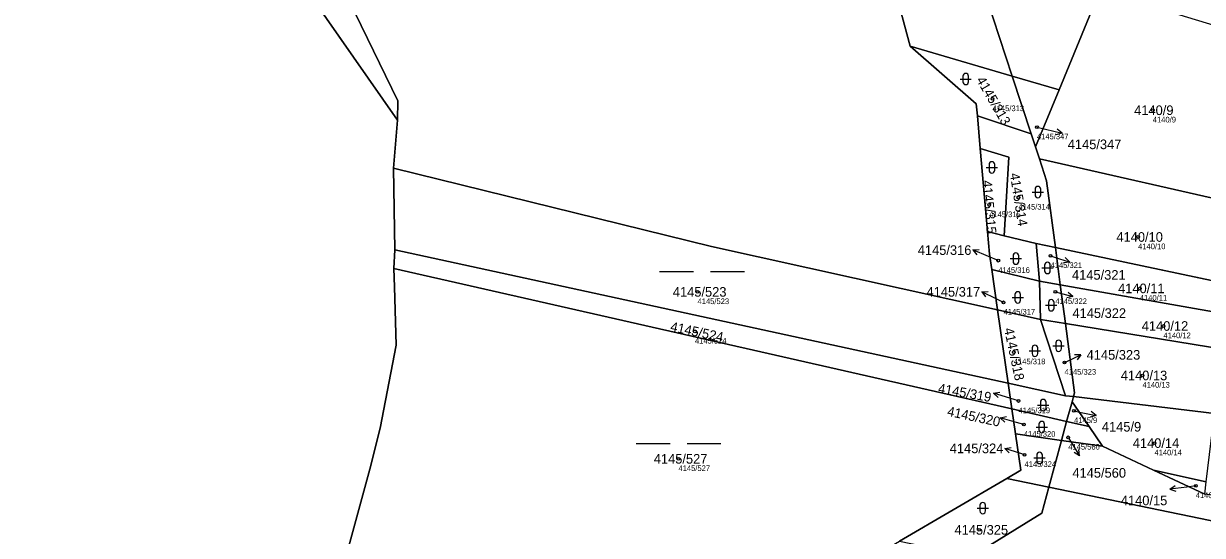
# Model space of a CAD drawing. Extents: x -739214 to -733252, y -1147612 to -1142842.
# Drawn here: x -736257.4 to -736049, y -1146646.4 to -1146556 of the extents above; entities that cross this region are included whole.
import ezdxf

# ---------------------------------------------------------------- set-up
doc = ezdxf.new("R2010")
doc.units = 0
for name, color, linetype in [('Definiční body', 7, 'Continuous'), ('Hranice parcel', 7, 'Continuous'), ('Parcelní čísla', 7, 'Continuous'), ('Polygon parcely', 7, 'Continuous'), ('Pop  PČ popisy', 7, 'Continuous'), ('Značky kultur', 7, 'Continuous')]:
    doc.layers.add(name, color=color, linetype=linetype)

msp = doc.modelspace()

# ---------------------------------------------------------------- linework, layer by layer
at = {"layer": 'Definiční body'}
for centre in [(-736086.12, -1146569.27), (-736057.78, -1146571.27), (-736078.26, -1146574.25), (-736086.7, -1146588.01), (-736081.54, -1146586.68), (-736060.38, -1146593.67), (-736085.09, -1146597.86), (-736075.86, -1146597), (-736138.25, -1146603.38), (-736075.01, -1146603.37), (-736060.08, -1146602.76), (-736084.16, -1146605.23), (-736138.71, -1146610.36), (-736055.9, -1146609.41), (-736082.35, -1146614.01), (-736073.38, -1146615.86), (-736059.61, -1146618.15), (-736081.52, -1146622.66), (-736071.7, -1146624.41), (-736080.57, -1146626.83), (-736072.73, -1146629.1), (-736057.49, -1146630.11), (-736141.62, -1146632.89), (-736080.46, -1146632.17), (-736050.19, -1146637.67), (-736088.47, -1146645.44)]:
    msp.add_circle(centre, 0.25, dxfattribs=at)
at = {"layer": 'Hranice parcel'}
for p, q in [((-736216.79, -1146536.45), (-736191.26, -1146573.01)), ((-736100.68, -1146559.92), (-736082.62, -1146565.24)), ((-736100.68, -1146559.92), (-736088.98, -1146570.14)), ((-736082.62, -1146565.24), (-736074.36, -1146567.67)), ((-736079.28, -1146575.43), (-736082.62, -1146565.24)), ((-736074.36, -1146567.67), (-736078.52, -1146577.76)), ((-736088.98, -1146570.14), (-736088.79, -1146572.26)), ((-736191.26, -1146573.01), (-736191.97, -1146581.49)), ((-736088.79, -1146572.26), (-736079.28, -1146575.43)), ((-736088.79, -1146572.26), (-736088.28, -1146578.06)), ((-736078.52, -1146577.76), (-736079.28, -1146575.43)), ((-736088.28, -1146578.06), (-736087, -1146592.71)), ((-736078.52, -1146577.76), (-736077.83, -1146579.87)), ((-736191.97, -1146581.49), (-736191.78, -1146595.93)), ((-736077.83, -1146579.87), (-736041, -1146588.22)), ((-736087, -1146592.71), (-736084.04, -1146593.47)), ((-736084.04, -1146593.47), (-736078.4, -1146594.8)), ((-736191.78, -1146595.93), (-736191.94, -1146599.24)), ((-736191.78, -1146595.93), (-736083.34, -1146619.53)), ((-736078.4, -1146594.8), (-736075.01, -1146595.52)), ((-736077.83, -1146601.47), (-736078.4, -1146594.8)), ((-736075.01, -1146595.52), (-736043.25, -1146602.28)), ((-736075.01, -1146595.52), (-736074.14, -1146602.12)), ((-736191.94, -1146599.24), (-736082.68, -1146624.08)), ((-736086.25, -1146599.44), (-736077.83, -1146601.47)), ((-736086.25, -1146599.44), (-736085.22, -1146606.58)), ((-736077.61, -1146608.26), (-736077.83, -1146601.47)), ((-736077.83, -1146601.47), (-736074.14, -1146602.12)), ((-736074.14, -1146602.12), (-736044.08, -1146607.44)), ((-736074.14, -1146602.12), (-736073.24, -1146608.97)), ((-736085.22, -1146606.58), (-736077.61, -1146608.26)), ((-736085.22, -1146606.58), (-736083.34, -1146619.53)), ((-736073.24, -1146621.73), (-736077.61, -1146608.26)), ((-736077.61, -1146608.26), (-736073.24, -1146608.97)), ((-736073.24, -1146608.97), (-736045.06, -1146613.54)), ((-736083.34, -1146619.53), (-736073.24, -1146621.73)), ((-736083.34, -1146619.53), (-736082.68, -1146624.08)), ((-736071.82, -1146621.9), (-736073.24, -1146621.73)), ((-736072.06, -1146622.79), (-736073.01, -1146626.28)), ((-736071.82, -1146621.9), (-736072.06, -1146622.79)), ((-736069.06, -1146627.18), (-736072.06, -1146622.79)), ((-736071.82, -1146621.9), (-736046.87, -1146624.86)), ((-736082.68, -1146624.08), (-736073.01, -1146626.28)), ((-736082.68, -1146624.08), (-736082.04, -1146628.49)), ((-736073.92, -1146629.63), (-736073.01, -1146626.28)), ((-736073.01, -1146626.28), (-736069.06, -1146627.18)), ((-736069.06, -1146627.18), (-736066.69, -1146630.64)), ((-736082.04, -1146628.49), (-736073.92, -1146629.63)), ((-736076.17, -1146637.88), (-736073.92, -1146629.63)), ((-736073.92, -1146629.63), (-736066.69, -1146630.64)), ((-736066.69, -1146630.64), (-736057.67, -1146634.87)), ((-736057.67, -1146634.87), (-736048.33, -1146636.94)), ((-736057.67, -1146634.87), (-736048.59, -1146639.13)), ((-736083.6, -1146636.35), (-736102.54, -1146647.43)), ((-736083.6, -1146636.35), (-736076.17, -1146637.88)), ((-736076.17, -1146637.88), (-736001.45, -1146653.31))]:
    msp.add_line(p, q, dxfattribs=at)
for points in [[(-736191.26, -1146573.01), (-736191.2, -1146569.6), (-736240.72, -1146467.85)], [(-736142.92, -1146500.2), (-736123.16, -1146523.78), (-736105.39, -1146542.41), (-736100.68, -1146559.92)], [(-736082.62, -1146565.24), (-736094.95, -1146527.58), (-736116.32, -1146499.99)], [(-736067.53, -1146550.01), (-736067.66, -1146551.39), (-736074.36, -1146567.67)], [(-736088.28, -1146578.06), (-736083.25, -1146579.57), (-736084.04, -1146593.47)], [(-736191.97, -1146581.49), (-736135.8, -1146595.37), (-736085.22, -1146606.58)], [(-736077.83, -1146579.87), (-736076.55, -1146583.77), (-736075.01, -1146595.52)], [(-736087, -1146592.71), (-736086.65, -1146596.69), (-736086.25, -1146599.44)], [(-736191.94, -1146599.24), (-736191.82, -1146602.51), (-736191.51, -1146612.78), (-736194.36, -1146627.44), (-736196.17, -1146634.72), (-736200.09, -1146648.96)], [(-736073.24, -1146608.97), (-736071.64, -1146621.23), (-736071.82, -1146621.9)], [(-736082.04, -1146628.49), (-736081.11, -1146634.89), (-736083.6, -1146636.35)], [(-736089.74, -1146650.09), (-736077.42, -1146642.47), (-736076.17, -1146637.88)]]:
    msp.add_lwpolyline(points, dxfattribs=at)
at = {"layer": 'Polygon parcely'}
for points in [[(-736191.2, -1146569.6), (-736240.72, -1146467.85), (-736248.59, -1146469.28), (-736216.79, -1146536.45), (-736191.26, -1146573.01)], [(-736094.95, -1146527.58), (-736116.32, -1146499.99), (-736146.34, -1146489.4), (-736142.92, -1146500.2), (-736123.16, -1146523.78), (-736105.39, -1146542.41), (-736100.68, -1146559.92), (-736082.62, -1146565.24)], [(-736074.36, -1146567.67), (-736067.66, -1146551.39), (-736067.53, -1146550.01), (-736066.51, -1146539.58), (-736066.95, -1146526.54), (-736067.27, -1146517.23), (-736116.32, -1146499.99), (-736094.95, -1146527.58), (-736082.62, -1146565.24)], [(-736074.36, -1146567.67), (-736078.52, -1146577.76), (-736077.83, -1146579.87), (-736041, -1146588.22), (-736038.99, -1146575.71), (-736035.66, -1146559.73), (-736067.53, -1146550.01), (-736067.66, -1146551.39)], [(-736088.98, -1146570.14), (-736088.79, -1146572.26), (-736079.28, -1146575.43), (-736082.62, -1146565.24), (-736100.68, -1146559.92)], [(-736078.52, -1146577.76), (-736074.36, -1146567.67), (-736082.62, -1146565.24), (-736079.28, -1146575.43)], [(-736088.28, -1146578.06), (-736083.25, -1146579.57), (-736084.04, -1146593.47), (-736078.4, -1146594.8), (-736075.01, -1146595.52), (-736076.55, -1146583.77), (-736077.83, -1146579.87), (-736078.52, -1146577.76), (-736079.28, -1146575.43), (-736088.79, -1146572.26)], [(-736087, -1146592.71), (-736084.04, -1146593.47), (-736083.25, -1146579.57), (-736088.28, -1146578.06)], [(-736083.34, -1146619.53), (-736085.22, -1146606.58), (-736135.8, -1146595.37), (-736191.97, -1146581.49), (-736191.78, -1146595.93)], [(-736043.25, -1146602.28), (-736041, -1146588.22), (-736077.83, -1146579.87), (-736076.55, -1146583.77), (-736075.01, -1146595.52)], [(-736086.65, -1146596.69), (-736086.25, -1146599.44), (-736077.83, -1146601.47), (-736078.4, -1146594.8), (-736084.04, -1146593.47), (-736087, -1146592.71)], [(-736082.68, -1146624.08), (-736083.34, -1146619.53), (-736191.78, -1146595.93), (-736191.94, -1146599.24)], [(-736074.14, -1146602.12), (-736075.01, -1146595.52), (-736078.4, -1146594.8), (-736077.83, -1146601.47)], [(-736044.08, -1146607.44), (-736043.25, -1146602.28), (-736075.01, -1146595.52), (-736074.14, -1146602.12)], [(-736191.51, -1146612.78), (-736194.36, -1146627.44), (-736196.17, -1146634.72), (-736200.09, -1146648.96), (-736167.56, -1146656.18), (-736132.29, -1146663.24), (-736131.9, -1146662.5), (-736122.58, -1146659.16), (-736112.56, -1146653.29), (-736102.54, -1146647.43), (-736083.6, -1146636.35), (-736081.11, -1146634.89), (-736082.04, -1146628.49), (-736082.68, -1146624.08), (-736191.94, -1146599.24), (-736191.82, -1146602.51)], [(-736085.22, -1146606.58), (-736077.61, -1146608.26), (-736077.83, -1146601.47), (-736086.25, -1146599.44)], [(-736073.24, -1146608.97), (-736074.14, -1146602.12), (-736077.83, -1146601.47), (-736077.61, -1146608.26)], [(-736074.14, -1146602.12), (-736073.24, -1146608.97), (-736045.06, -1146613.54), (-736044.08, -1146607.44)], [(-736073.24, -1146621.73), (-736077.61, -1146608.26), (-736085.22, -1146606.58), (-736083.34, -1146619.53)], [(-736071.82, -1146621.9), (-736071.64, -1146621.23), (-736073.24, -1146608.97), (-736077.61, -1146608.26), (-736073.24, -1146621.73)], [(-736073.24, -1146608.97), (-736071.64, -1146621.23), (-736071.82, -1146621.9), (-736046.87, -1146624.86), (-736045.06, -1146613.54)], [(-736073.01, -1146626.28), (-736072.06, -1146622.79), (-736071.82, -1146621.9), (-736073.24, -1146621.73), (-736083.34, -1146619.53), (-736082.68, -1146624.08)], [(-736072.06, -1146622.79), (-736073.01, -1146626.28), (-736069.06, -1146627.18)], [(-736048.33, -1146636.94), (-736046.87, -1146624.86), (-736071.82, -1146621.9), (-736072.06, -1146622.79), (-736069.06, -1146627.18), (-736066.69, -1146630.64), (-736057.67, -1146634.87)], [(-736082.04, -1146628.49), (-736073.92, -1146629.63), (-736073.01, -1146626.28), (-736082.68, -1146624.08)], [(-736073.92, -1146629.63), (-736066.69, -1146630.64), (-736069.06, -1146627.18), (-736073.01, -1146626.28)], [(-736081.11, -1146634.89), (-736083.6, -1146636.35), (-736076.17, -1146637.88), (-736073.92, -1146629.63), (-736082.04, -1146628.49)], [(-736001.45, -1146653.31), (-736024.71, -1146642.17), (-736048.59, -1146639.13), (-736057.67, -1146634.87), (-736066.69, -1146630.64), (-736073.92, -1146629.63), (-736076.17, -1146637.88)], [(-736048.59, -1146639.13), (-736048.33, -1146636.94), (-736057.67, -1146634.87)], [(-736089.74, -1146650.09), (-736077.42, -1146642.47), (-736076.17, -1146637.88), (-736083.6, -1146636.35), (-736102.54, -1146647.43)], [(-735980.05, -1146665.11), (-736001.45, -1146653.31), (-736076.17, -1146637.88), (-736077.42, -1146642.47), (-736089.74, -1146650.09), (-736037.76, -1146661.36), (-735972.21, -1146674.51)]]:
    msp.add_lwpolyline(points, close=True, dxfattribs=at)
for points in [[(-736240.72, -1146467.85), (-736191.2, -1146569.6), (-736191.26, -1146573.01), (-736191.97, -1146581.49), (-736135.8, -1146595.37), (-736085.22, -1146606.58), (-736086.25, -1146599.44), (-736086.65, -1146596.69), (-736087, -1146592.71), (-736088.28, -1146578.06), (-736088.79, -1146572.26), (-736088.98, -1146570.14), (-736100.68, -1146559.92), (-736105.39, -1146542.41)], [(-736446.12, -1146664.77), (-736250, -1146692.16), (-736227.9, -1146695.24), (-736223.78, -1146688.92), (-736215.38, -1146679.7), (-736206.12, -1146668.34), (-736205.38, -1146667.25), (-736200.09, -1146648.96), (-736196.17, -1146634.72), (-736194.36, -1146627.44), (-736191.51, -1146612.78), (-736191.82, -1146602.51), (-736191.94, -1146599.24), (-736191.78, -1146595.93), (-736191.97, -1146581.49), (-736191.26, -1146573.01), (-736216.79, -1146536.45)]]:
    msp.add_lwpolyline(points, dxfattribs=at)
at = {"layer": 'Pop  PČ popisy'}
for p, q in [((-736078.26, -1146574.25), (-736076.74, -1146574.62)), ((-736076.74, -1146574.62), (-736073.83, -1146575.35)), ((-736073.83, -1146575.35), (-736074.92, -1146575.59)), ((-736073.83, -1146575.35), (-736074.68, -1146574.62)), ((-736089.58, -1146595.97), (-736088.46, -1146595.9)), ((-736086.82, -1146597.14), (-736089.58, -1146595.97)), ((-736089.58, -1146595.97), (-736088.86, -1146596.82)), ((-736085.09, -1146597.86), (-736086.82, -1146597.14)), ((-736075.86, -1146597), (-736075.31, -1146597.18)), ((-736075.31, -1146597.18), (-736072.46, -1146598.11)), ((-736072.46, -1146598.11), (-736073.56, -1146598.27)), ((-736072.46, -1146598.11), (-736073.25, -1146597.32)), ((-736088.03, -1146603.35), (-736086.91, -1146603.34)), ((-736085.33, -1146604.67), (-736088.03, -1146603.35)), ((-736088.03, -1146603.35), (-736087.35, -1146604.24)), ((-736075.01, -1146603.37), (-736074.79, -1146603.43)), ((-736074.79, -1146603.43), (-736071.89, -1146604.21)), ((-736071.89, -1146604.21), (-736072.99, -1146604.43)), ((-736071.89, -1146604.21), (-736072.73, -1146603.46)), ((-736084.16, -1146605.23), (-736085.33, -1146604.67)), ((-736073.2, -1146615.78), (-736070.48, -1146614.51)), ((-736070.48, -1146614.51), (-736071.6, -1146614.48)), ((-736070.48, -1146614.51), (-736071.18, -1146615.39)), ((-736073.38, -1146615.86), (-736073.2, -1146615.78)), ((-736085.93, -1146621.3), (-736084.83, -1146621.12)), ((-736083.06, -1146622.18), (-736085.93, -1146621.3)), ((-736085.93, -1146621.3), (-736085.12, -1146622.07)), ((-736081.52, -1146622.66), (-736083.06, -1146622.18)), ((-736071.7, -1146624.41), (-736070.72, -1146624.62)), ((-736070.72, -1146624.62), (-736067.79, -1146625.24)), ((-736067.79, -1146625.24), (-736068.87, -1146625.53)), ((-736067.79, -1146625.24), (-736068.66, -1146624.55)), ((-736084.78, -1146625.63), (-736083.67, -1146625.43)), ((-736081.89, -1146626.46), (-736084.78, -1146625.63)), ((-736084.78, -1146625.63), (-736083.95, -1146626.39)), ((-736080.57, -1146626.83), (-736081.89, -1146626.46)), ((-736072.73, -1146629.1), (-736072.31, -1146629.79)), ((-736083.94, -1146631.04), (-736082.84, -1146630.88)), ((-736081.09, -1146631.97), (-736083.94, -1146631.04)), ((-736083.94, -1146631.04), (-736083.15, -1146631.83)), ((-736072.31, -1146629.79), (-736070.76, -1146632.36)), ((-736070.76, -1146632.36), (-736070.85, -1146631.25)), ((-736080.46, -1146632.17), (-736081.09, -1146631.97)), ((-736070.76, -1146632.36), (-736071.71, -1146631.76)), ((-736054.76, -1146638.25), (-736053.83, -1146637.63)), ((-736051.78, -1146637.88), (-736054.76, -1146638.25)), ((-736050.19, -1146637.67), (-736051.78, -1146637.88)), ((-736054.76, -1146638.25), (-736053.7, -1146638.62))]:
    msp.add_line(p, q, dxfattribs=at)
at = {"layer": 'Značky kultur'}
for p, q in [((-736091.86, -1146565.75), (-736089.86, -1146565.75)), ((-736091.36, -1146565.25), (-736091.36, -1146566.25)), ((-736090.36, -1146566.25), (-736090.36, -1146565.25)), ((-736087.22, -1146581.37), (-736085.22, -1146581.37)), ((-736086.72, -1146580.87), (-736086.72, -1146581.87)), ((-736085.72, -1146581.87), (-736085.72, -1146580.87)), ((-736079.09, -1146585.73), (-736077.09, -1146585.73)), ((-736078.59, -1146585.23), (-736078.59, -1146586.23)), ((-736077.59, -1146586.23), (-736077.59, -1146585.23)), ((-736082.99, -1146597.5), (-736080.99, -1146597.5)), ((-736082.49, -1146597), (-736082.49, -1146598)), ((-736081.49, -1146598), (-736081.49, -1146597)), ((-736144.98, -1146599.75), (-736138.98, -1146599.75)), ((-736135.98, -1146599.75), (-736129.98, -1146599.75)), ((-736077.4, -1146599.15), (-736075.4, -1146599.15)), ((-736076.9, -1146598.65), (-736076.9, -1146599.65)), ((-736075.9, -1146599.65), (-736075.9, -1146598.65)), ((-736082.66, -1146604.35), (-736080.66, -1146604.35)), ((-736082.16, -1146603.85), (-736082.16, -1146604.85)), ((-736081.16, -1146604.85), (-736081.16, -1146603.85)), ((-736076.73, -1146605.75), (-736074.73, -1146605.75)), ((-736076.23, -1146605.25), (-736076.23, -1146606.25)), ((-736075.23, -1146606.25), (-736075.23, -1146605.25)), ((-736074.93, -1146612.41), (-736074.93, -1146613.41)), ((-736073.93, -1146613.41), (-736073.93, -1146612.41)), ((-736079.61, -1146613.79), (-736077.61, -1146613.79)), ((-736079.11, -1146613.29), (-736079.11, -1146614.29)), ((-736078.11, -1146614.29), (-736078.11, -1146613.29)), ((-736075.43, -1146612.91), (-736073.43, -1146612.91)), ((-736077.66, -1146622.89), (-736077.66, -1146623.89)), ((-736076.66, -1146623.89), (-736076.66, -1146622.89)), ((-736078.16, -1146623.39), (-736076.16, -1146623.39)), ((-736078.42, -1146627.27), (-736076.42, -1146627.27)), ((-736077.92, -1146626.77), (-736077.92, -1146627.77)), ((-736076.92, -1146627.77), (-736076.92, -1146626.77)), ((-736149.11, -1146630.19), (-736143.11, -1146630.19)), ((-736140.11, -1146630.19), (-736134.11, -1146630.19)), ((-736078.81, -1146632.74), (-736076.81, -1146632.74)), ((-736078.31, -1146632.24), (-736078.31, -1146633.24)), ((-736077.31, -1146633.24), (-736077.31, -1146632.24)), ((-736088.85, -1146641.6), (-736086.85, -1146641.6)), ((-736088.35, -1146641.1), (-736088.35, -1146642.1)), ((-736087.35, -1146642.1), (-736087.35, -1146641.1))]:
    msp.add_line(p, q, dxfattribs=at)
for centre, start, end in [((-736090.86, -1146565.25), 0, 180), ((-736090.86, -1146566.25), 180, 359.9879), ((-736086.22, -1146580.87), 0, 180), ((-736086.22, -1146581.87), 180, 359.9879), ((-736078.09, -1146585.23), 0, 180), ((-736078.09, -1146586.23), 180, 359.9879), ((-736081.99, -1146597), 0, 180), ((-736081.99, -1146598), 180, 359.9879), ((-736076.4, -1146598.65), 0, 180), ((-736076.4, -1146599.65), 180, 359.9879), ((-736081.66, -1146603.85), 0, 180), ((-736081.66, -1146604.85), 180, 359.9879), ((-736075.73, -1146605.25), 0, 180), ((-736075.73, -1146606.25), 180, 359.9879), ((-736078.61, -1146613.29), 0, 180), ((-736074.43, -1146612.41), 0, 180), ((-736078.61, -1146614.29), 180, 359.9879), ((-736074.43, -1146613.41), 180, 359.9879), ((-736077.16, -1146622.89), 0, 180), ((-736077.16, -1146623.89), 180, 359.9879), ((-736077.42, -1146626.77), 0, 180), ((-736077.42, -1146627.77), 180, 359.9879), ((-736077.81, -1146632.24), 0, 180), ((-736077.81, -1146633.24), 180, 359.9879), ((-736087.85, -1146641.1), 0, 180), ((-736087.85, -1146642.1), 180, 359.9879)]:
    msp.add_arc(centre, 0.5, start, end, dxfattribs=at)

# ---------------------------------------------------------------- texts
at = {"layer": 'Definiční body'}
for s, p in [('4145/313', (-736086.12, -1146571.43)), ('4140/9', (-736057.78, -1146573.43)), ('4145/347', (-736078.26, -1146576.41)), ('4145/314', (-736081.54, -1146588.84)), ('4145/315', (-736086.7, -1146590.17)), ('4140/10', (-736060.38, -1146595.83)), ('4145/321', (-736075.86, -1146599.16)), ('4145/316', (-736085.09, -1146600.02)), ('4145/523', (-736138.25, -1146605.54)), ('4145/322', (-736075.01, -1146605.53)), ('4140/11', (-736060.08, -1146604.92)), ('4145/317', (-736084.16, -1146607.39)), ('4140/12', (-736055.9, -1146611.57)), ('4145/524', (-736138.71, -1146612.52)), ('4145/318', (-736082.35, -1146616.17)), ('4145/323', (-736073.38, -1146618.02)), ('4140/13', (-736059.61, -1146620.31)), ('4145/319', (-736081.52, -1146624.82)), ('4145/9', (-736071.7, -1146626.57)), ('4145/320', (-736080.57, -1146628.99)), ('4145/560', (-736072.73, -1146631.26)), ('4140/14', (-736057.49, -1146632.27)), ('4145/324', (-736080.46, -1146634.33)), ('4145/527', (-736141.62, -1146635.05)), ('4140/15', (-736050.19, -1146639.83))]:
    msp.add_text(s, height=1, dxfattribs=at).set_placement(p)
at = {"layer": 'Parcelní čísla'}
for s, rotation, p in [('4145/313', 300, (-736089.04, -1146565.91)), ('4145/314', 279, (-736083.06, -1146582.5)), ('4145/315', 275, (-736087.93, -1146583.73)), ('4145/524', 348, (-736143.16, -1146610.28)), ('4145/318', 282, (-736084.09, -1146609.91)), ('4145/319', 350, (-736095.84, -1146621.21)), ('4145/320', 348, (-736094.23, -1146625.25))]:
    msp.add_text(s, height=1.7, rotation=rotation, dxfattribs=at).set_placement(p)
for s, p in [('4140/9', (-736061.08, -1146572.12)), ('4145/347', (-736072.82, -1146578.15)), ('4140/10', (-736064.22, -1146594.52)), ('4145/316', (-736099.33, -1146596.84)), ('4145/321', (-736072.07, -1146601.23)), ('4145/523', (-736142.62, -1146604.23)), ('4145/317', (-736097.78, -1146604.22)), ('4140/11', (-736063.92, -1146603.61)), ('4145/322', (-736071.99, -1146607.98)), ('4140/12', (-736059.74, -1146610.26)), ('4145/323', (-736069.48, -1146615.36)), ('4140/13', (-736063.45, -1146619)), ('4145/9', (-736066.79, -1146628.07)), ('4140/14', (-736061.33, -1146630.96)), ('4145/324', (-736093.68, -1146631.89)), ('4145/527', (-736145.99, -1146633.74)), ('4145/560', (-736072, -1146636.22)), ('4140/15', (-736063.44, -1146641.09)), ('4145/325', (-736092.84, -1146646.29))]:
    msp.add_text(s, height=1.7, dxfattribs=at).set_placement(p)

doc.saveas('drawing.dxf')
